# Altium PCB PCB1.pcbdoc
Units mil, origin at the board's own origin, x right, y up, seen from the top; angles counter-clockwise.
Board outline 1390.26 x 2970.46 mil, 2 copper layers (Top Layer, Bottom Layer); 11 components, 15 nets, 46 pads, 12 vias.
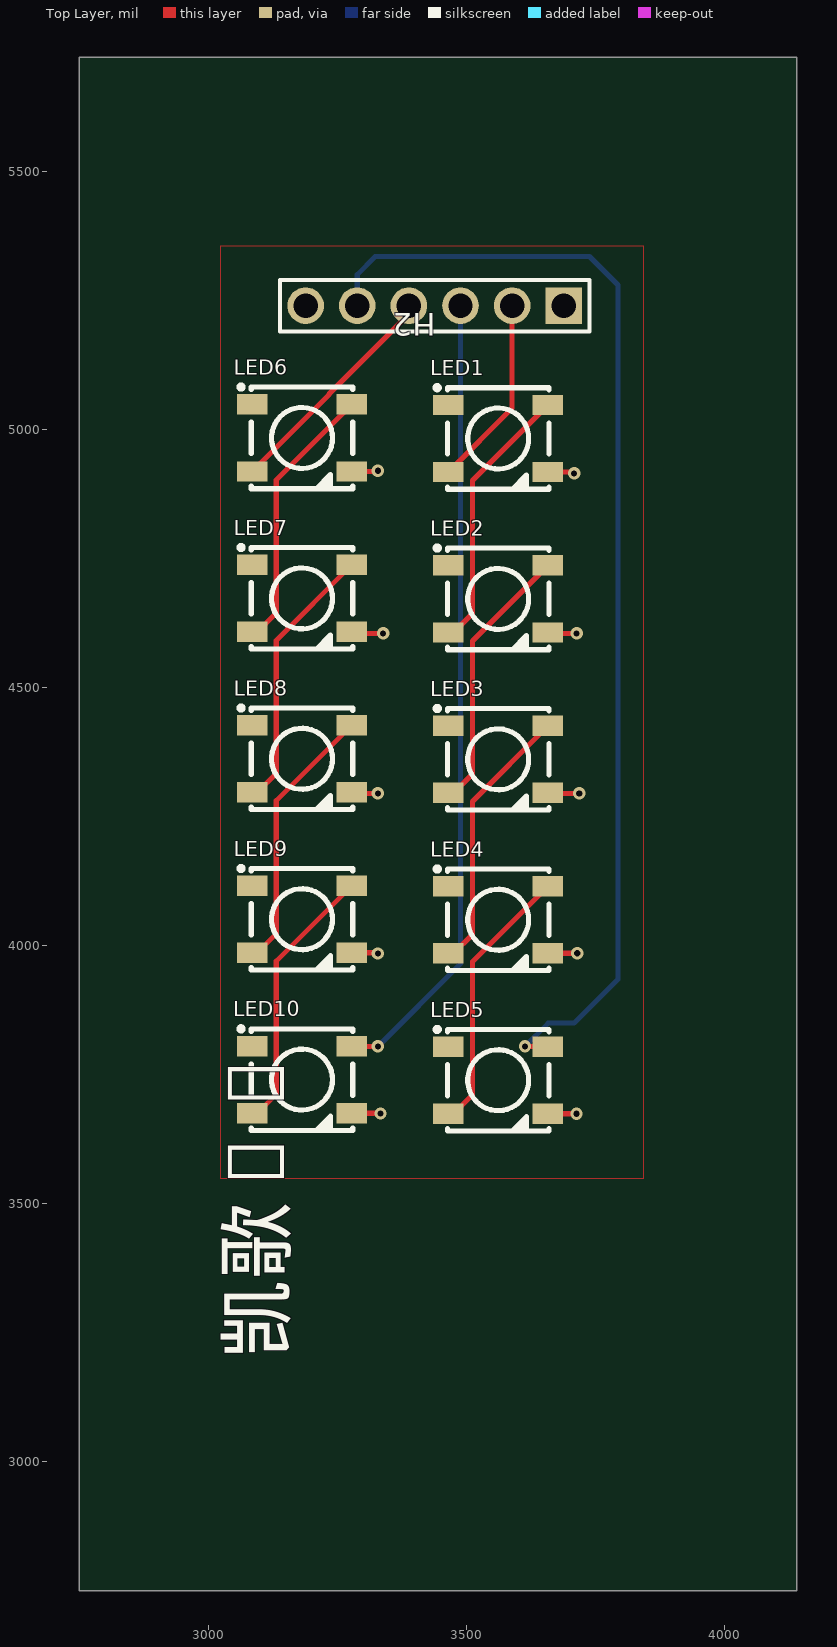
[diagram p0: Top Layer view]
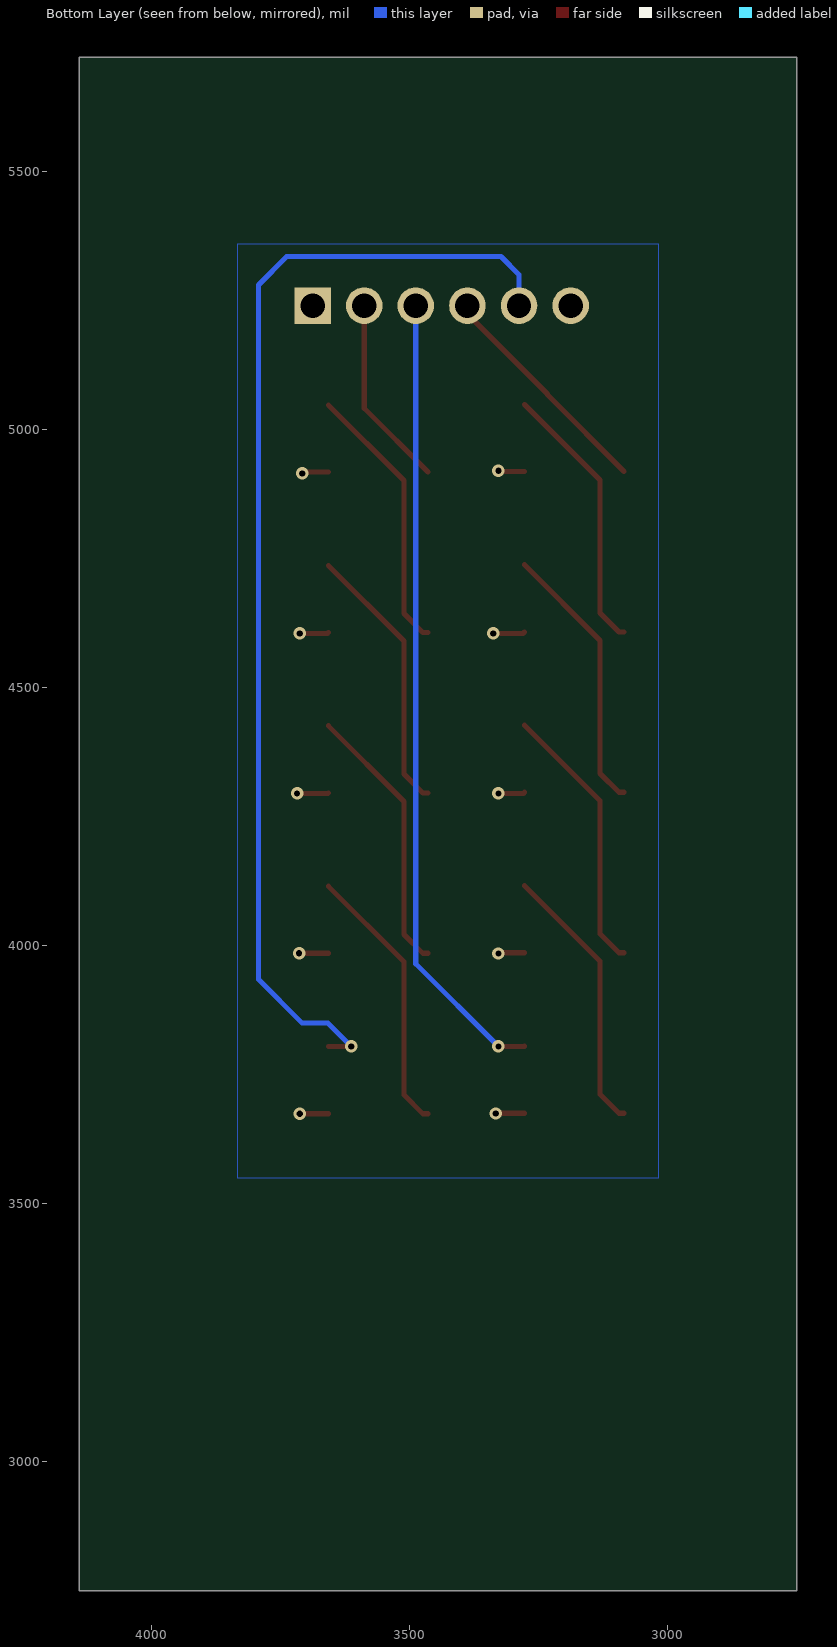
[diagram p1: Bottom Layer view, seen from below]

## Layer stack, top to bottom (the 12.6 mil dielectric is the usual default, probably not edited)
Top Solder: solder mask 0.4, Solder Resist, Dk 3.5
Top Layer: signal copper 1.4
Dielectric 1: dielectric 12.6, FR-4, Dk 4.8
Bottom Layer: signal copper 1.4
Bottom Solder: solder mask 0.4, Solder Resist, Dk 3.5

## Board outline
4140.26,2750 2750,2750 2750,5720.46 4140.26,5720.46

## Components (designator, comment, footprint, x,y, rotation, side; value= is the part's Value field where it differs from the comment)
H2 "" HDR-TH_6P-P2.54-V-M-1 3438.41,5239.43 r180 top
LED1 "" LED-SMD_4P-L5.0-W5.0-TL_WS2812B-B 3561.39,4982.07 r0 top
LED2 "" LED-SMD_4P-L5.0-W5.0-TL_WS2812B-B 3561.39,4671.28 r0 top
LED3 "" LED-SMD_4P-L5.0-W5.0-TL_WS2812B-B 3561.39,4360.5 r0 top
LED4 "" LED-SMD_4P-L5.0-W5.0-TL_WS2812B-B 3561.39,4049.71 r0 top
LED5 "" LED-SMD_4P-L5.0-W5.0-TL_WS2812B-B 3561.39,3738.92 r0 top
LED6 "" LED-SMD_4P-L5.0-W5.0-TL_WS2812B-B 3181.39,4983.14 r0 top
LED7 "" LED-SMD_4P-L5.0-W5.0-TL_WS2812B-B 3181.39,4672.35 r0 top
LED8 "" LED-SMD_4P-L5.0-W5.0-TL_WS2812B-B 3181.39,4361.57 r0 top
LED9 "" LED-SMD_4P-L5.0-W5.0-TL_WS2812B-B 3181.39,4050.78 r0 top
LED10 "" LED-SMD_4P-L5.0-W5.0-TL_WS2812B-B 3181.39,3739.99 r0 top

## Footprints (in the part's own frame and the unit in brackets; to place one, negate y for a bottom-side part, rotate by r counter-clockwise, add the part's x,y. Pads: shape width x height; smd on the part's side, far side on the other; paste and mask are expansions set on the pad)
HDR-TH_6P-P2.54-V-M-1 [mil]
  rect 70.9x70.9 hole 47.2: 1(-250,0)
  round 70.9 hole 47.2: 2(-150,0) 3(-50,0) 4(50,0) 5(150,0) 6(250,0)
  silkscreen extent -300,-50 300,50
LED-SMD_4P-L5.0-W5.0-TL_WS2812B-B [mm]
  rect 1.5x1 smd: 1(-2.45,1.65) 2(-2.45,-1.65) 3(2.45,-1.65) 4(2.45,1.65)
  silkscreen extent -3.1,-2.5 2.5,2.6

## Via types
v1: diameter 24.02, hole 12.01, Top Layer to Bottom Layer, 12 vias

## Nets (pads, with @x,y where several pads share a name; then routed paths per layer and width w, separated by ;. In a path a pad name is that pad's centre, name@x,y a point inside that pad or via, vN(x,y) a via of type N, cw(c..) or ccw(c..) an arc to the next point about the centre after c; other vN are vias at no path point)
$1N1169: LED1.4 LED2.2 | length 526.4
  Top Layer w10: LED2.2 3474.78,4606.32 3511.46,4643.01 3511.46,4900.65 LED1.4
$1N1176: LED2.4 LED3.2 | length 526.4
  Top Layer w10: LED3.2 3474.78,4295.54 3511.46,4332.22 3511.46,4589.86 LED2.4
$1N1183: LED3.4 LED4.2 | length 526.4
  Top Layer w10: LED4.2 3474.78,3984.75 3511.46,4021.44 3511.46,4279.07 LED3.4
$1N1190: LED4.4 LED5.2 | length 526.4
  Top Layer w10: LED5.2 3474.78,3673.96 3511.46,3710.65 3511.46,3968.29 LED4.4
$1N1197: LED9.4 LED10.2 | length 526.4
  Top Layer w10: LED10.2 3094.78,3675.03 3131.46,3711.72 3131.46,3969.36 LED9.4
$1N1204: LED8.4 LED9.2 | length 526.4
  Top Layer w10: LED9.2 3094.78,3985.82 3131.46,4022.51 3131.46,4280.14 LED8.4
$1N1214: LED6.4 LED7.2 | length 526.4
  Top Layer w10: LED7.2 3094.78,4607.39 3131.46,4644.08 3131.46,4901.72 LED6.4
$1N1230: LED7.4 LED8.2 | length 526.4
  Top Layer w10: LED8.2 3094.78,4296.61 3131.46,4333.29 3131.46,4590.93 LED7.4
DI0: H2.5 LED5.4 | length 2225.8
  Top Layer w10: v1(3613.41,3804.43) 3657.3,3804.43 LED5.4
  Bottom Layer w10: H2.5 3288.41,5299.43 3323.41,5334.43 3738.41,5334.43 3793.41,5279.43 3793.41,3934.43 3708.41,3849.43 3658.41,3849.43 v1(3613.41,3804.43)
DI1: H2.3 LED10.4 | length 1552.1
  Top Layer w10: LED10.4 3278.37,3804.43 v1(3328.41,3804.43)
  Bottom Layer w10: v1(3328.41,3804.43) 3488.41,3964.43 H2.3
DO0: H2.2 LED1.2 | length 373.5
  Top Layer w10: LED1.2 3588.41,5040.58 H2.2
DO1: H2.4 LED6.2 | length 447
  Top Layer w10: LED6.2 3233.41,5066.65 3233.41,5068.43 3388.41,5223.43 H2.4
GND: H2.6 LED1.3 LED2.3 LED3.3 LED4.3 LED5.3 LED6.3 LED7.3 LED8.3 LED9.3 LED10.3 | length 552.3
  Top Layer w10: LED10.3 3332.8,3675.03 v1(3333.41,3674.43) ; LED9.3 3327.02,3985.82 v1(3328.41,3984.43) ; LED8.3 3280.03,4294.43 v1(3328.41,4294.43) ; LED7.3 3280.81,4604.43 v1(3338.41,4604.43) ; LED6.3 3327.16,4918.18 v1(3328.41,4919.43) ; LED5.3 v1(3713.1,3673.96) ; LED4.3 v1(3714.53,3984.75) ; LED3.3 3658.96,4294.43 v1(3718.41,4294.43) ; LED2.3 3659.74,4604.43 v1(3713.41,4604.43) ; LED1.3 3705.73,4917.11 v1(3708.41,4914.43)
VCC: H2.1 LED1.1 LED2.1 LED3.1 LED4.1 LED5.1 LED6.1 LED7.1 LED8.1 LED9.1 LED10.1
"": 

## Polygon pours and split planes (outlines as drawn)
VCC on Top Layer (solid, remove dead copper): 3023.41,3549.43 3843.41,3549.43 3843.41,5354.43 3023.41,5354.43
GND on Bottom Layer (solid, remove dead copper, pour order 1): 3018.41,3549.43 3833.41,3549.43 3833.41,5359.43 3018.41,5359.43

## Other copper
Top Layer:
  pour cut-out net GND: 3702.37,4922.11 3687.37,4934.61 3687.37,4899.61 3702.37,4912.11
  pour cut-out net $1N1169: 3634.63,5016.74 3662.91,5027.34 3628.32,5042.25 3620.48,5016.74
  pour cut-out net GND: 3702.37,4599.43 3702.37,4609.43 3687.37,4621.93 3687.37,4586.93
  pour cut-out net $1N1176: 3634.63,4705.95 3662.91,4716.56 3628.32,4731.46 3620.48,4705.95
  pour cut-out net $1N1169: 3505.07,4629.54 3498,4636.61 3469.72,4626.01 3494.46,4601.26
  pour cut-out net GND: 3702.37,4289.43 3702.37,4299.43 3687.37,4311.93 3687.37,4276.93
  pour cut-out net $1N1183: 3634.63,4395.16 3662.91,4405.77 3628.32,4420.68 3620.48,4395.16
  pour cut-out net $1N1176: 3505.07,4318.76 3498,4325.83 3469.72,4315.22 3494.46,4290.47
  pour cut-out net GND: 3702.37,3989.75 3687.37,4002.25 3687.37,3967.25 3702.37,3979.75
  pour cut-out net $1N1190: 3634.63,4084.38 3662.91,4094.99 3628.32,4109.89 3620.48,4084.38
  pour cut-out net $1N1183: 3505.07,4007.97 3498,4015.04 3469.72,4004.44 3494.46,3979.69
  pour cut-out net GND: 3702.37,3668.96 3702.37,3678.96 3687.37,3691.46 3687.37,3656.46
  pour cut-out net $1N1190: 3505.07,3697.19 3498,3704.26 3469.72,3693.65 3494.46,3668.9
  pour cut-out net GND: 3322.37,4923.18 3307.37,4935.68 3307.37,4900.68 3322.37,4913.18
  pour cut-out net $1N1214: 3254.63,5017.81 3282.91,5028.41 3248.32,5043.32 3240.48,5017.81
  pour cut-out net DO1: 3108.16,4948.47 3079.87,4937.86 3114.46,4922.96 3122.3,4948.47
  pour cut-out net GND: 3322.37,4599.43 3322.37,4609.43 3307.37,4621.93 3307.37,4587.71
  pour cut-out net $1N1230: 3254.63,4707.02 3282.91,4717.63 3248.32,4732.53 3240.48,4707.02
  pour cut-out net $1N1214: 3125.07,4630.61 3118,4637.68 3089.72,4627.08 3114.46,4602.33
  pour cut-out net GND: 3322.37,4289.43 3322.37,4299.43 3307.37,4311.93 3307.37,4276.93
  pour cut-out net $1N1204: 3254.63,4396.23 3282.91,4406.84 3248.32,4421.75 3240.48,4396.23
  pour cut-out net $1N1230: 3125.07,4319.83 3118,4326.9 3089.72,4316.29 3114.46,4291.54
  pour cut-out net GND: 3322.37,3990.82 3307.37,4003.32 3307.37,3968.32 3322.37,3980.82
  pour cut-out net $1N1197: 3254.63,4085.45 3282.91,4096.06 3248.32,4110.96 3240.48,4085.45
  pour cut-out net $1N1204: 3125.07,4009.04 3118,4016.11 3089.72,4005.51 3114.46,3980.76
  pour cut-out net GND: 3322.37,3670.03 3322.37,3680.03 3307.37,3692.53 3307.37,3657.53
  pour cut-out net DI1: 3322.37,3799.43 3322.37,3809.43 3307.37,3821.93 3307.37,3786.93
  pour cut-out net $1N1197: 3125.07,3698.26 3118,3705.33 3089.72,3694.72 3114.46,3669.97
  pour cut-out net DO1: 3354.17,5230.24 3349.41,5191.5 3358.86,5186.81 3401.8,5206.61
  pour cut-out net GND: 3319.57,4927.56 3307.49,4923.18 3308.54,4913.18 3321.45,4909.64
  pour cut-out net GND: 3702.68,4924.98 3689.23,4922.11 3686.94,4912.11 3698.66,4907.42
  pour cut-out net GND: 3330.47,4613.43 3318,4609.43 3318,4599.43 3330.47,4595.42
  pour cut-out net GND: 3705.47,4613.43 3693,4609.43 3693,4599.43 3705.47,4595.42
  pour cut-out net GND: 3320.47,4303.43 3308,4299.43 3308,4289.43 3320.47,4285.42
  pour cut-out net GND: 3710.47,4303.43 3698,4299.43 3698,4289.43 3710.47,4285.42
  pour cut-out net GND: 3321.57,3994.29 3308.6,3990.82 3307.44,3980.82 3319.48,3976.4
  pour cut-out net GND: 3706.58,3993.76 3694.11,3989.75 3694.11,3979.75 3706.58,3975.74
  pour cut-out net GND: 3325.93,3683.82 3313.25,3680.03 3312.75,3670.03 3325.02,3665.84
  pour cut-out net GND: 3705.16,3682.97 3692.69,3678.96 3692.69,3668.96 3705.16,3664.96
  pour cut-out net DI1: 3320.47,3813.43 3308,3809.43 3308,3799.43 3320.47,3795.42
Bottom Layer:
  pour cut-out net DI1: 3461.82,5215.98 3483.41,5179.16 3493.41,5179.16 3515,5215.98
  pour cut-out net DI1: 3340.39,3803.68 3346.38,3815.33 3339.31,3822.4 3327.66,3816.41

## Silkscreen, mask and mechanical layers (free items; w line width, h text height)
Top Overlay:
  text "凯歌XE" at 3146.64,3200.69 h111.02 r90
Mechanical 1:
  lines w10: 3000,3011.56 3858.99,3011.56 3858.99,5380.11 3000,5380.11 3000,3011.56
